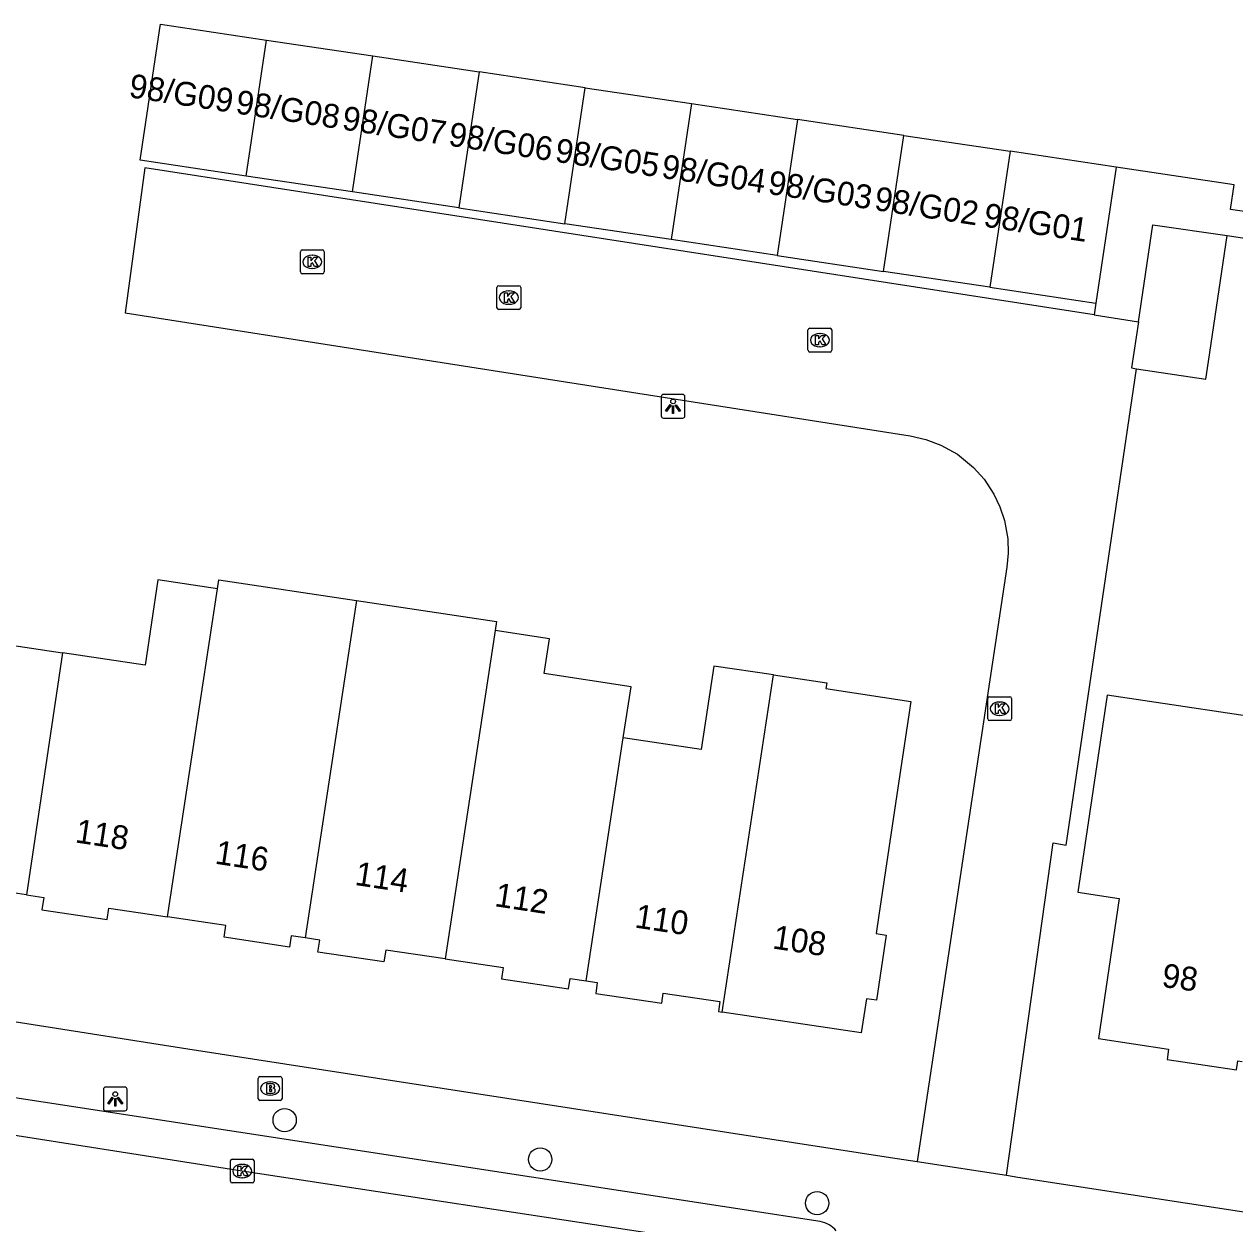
# Model space of a CAD drawing. Extents: x 161486 to 162249, y 379484 to 380829.
# Drawn here: x 161717.9 to 161768.8, y 380576 to 380626.4 of the extents above; entities that cross this region are included whole.
import ezdxf

# ---------------------------------------------------------------- set-up
doc = ezdxf.new("R2010")
doc.units = 0
for name, color, linetype in [('IMGEO_Boom', 7, 'Continuous'), ('IMGEO_Brandkraan', 7, 'Continuous'), ('IMGEO_Kolk', 7, 'Continuous'), ('IMGEO_Lichtpunt', 7, 'Continuous'), ('IMGEO_Pand', 7, 'Continuous'), ('IMGEO_Pand_nummerreeks', 7, 'Continuous'), ('IMGEO_Rijbaan_lokaal_open', 7, 'Continuous'), ('IMGEO_Voetpad_open', 7, 'Continuous')]:
    doc.layers.add(name, color=color, linetype=linetype)

msp = doc.modelspace()

# ---------------------------------------------------------------- linework, layer by layer
at = {"layer": 'IMGEO_Boom'}
for centre in [(161728.873, 380580.399), (161739.612, 380578.747), (161751.249, 380576.91)]:
    msp.add_circle(centre, 0.489, dxfattribs=at)
at = {"layer": 'IMGEO_Brandkraan'}
for p, q in [((161727.762, 380581.299), (161727.762, 380582.151)), ((161727.837, 380582.225), (161728.689, 380582.225)), ((161728.25, 380582.005), (161728.275, 380582.005)), ((161728.763, 380582.151), (161728.763, 380581.299)), ((161728.689, 380581.225), (161727.837, 380581.225)), ((161728.273, 380581.445), (161728.248, 380581.445))]:
    msp.add_line(p, q, dxfattribs=at)
for points in [[(161727.762, 380581.299), (161727.762, 380582.151)], [(161727.837, 380582.225), (161728.689, 380582.225)], [(161728.11, 380581.925), (161728.11, 380581.525), (161728.323, 380581.525)], [(161728.341, 380581.925), (161728.11, 380581.925)], [(161728.289, 380581.844), (161728.235, 380581.844), (161728.235, 380581.768)], [(161728.235, 380581.768), (161728.288, 380581.768)], [(161728.763, 380582.151), (161728.763, 380581.299)], [(161728.689, 380581.225), (161727.837, 380581.225)], [(161728.297, 380581.692), (161728.235, 380581.692), (161728.235, 380581.611)], [(161728.235, 380581.611), (161728.297, 380581.611)]]:
    msp.add_lwpolyline(points, dxfattribs=at)
for centre, radius, start, end in [((161727.839, 380582.149), 0.0765, 91.552, 178.448), ((161727.839, 380582.149), 0.0765, 91.552, 178.448), ((161728.29, 380581.806), 0.0379, 267.8285, 90.9355), ((161728.345, 380581.78), 0.145, 59.4692, 91.5367), ((161728.37, 380581.827), 0.0922, 285.5137, 58.1501), ((161728.375, 380581.635), 0.105, 301.3115, 78.989), ((161728.687, 380582.149), 0.0765, 1.552, 88.448), ((161728.687, 380582.149), 0.0765, 1.552, 88.448), ((161727.839, 380581.301), 0.0765, 181.552, 268.448), ((161727.839, 380581.301), 0.0765, 181.552, 268.448), ((161728.298, 380581.651), 0.0404, 269.8759, 90.5077), ((161728.329, 380581.776), 0.251, 268.6676, 293.5347), ((161728.687, 380581.301), 0.0765, 271.552, 358.448), ((161728.687, 380581.301), 0.0765, 271.552, 358.448)]:
    msp.add_arc(centre, radius, start, end, dxfattribs=at)
for centre, major_axis, ratio, start_param, end_param in [((161728.249, 380581.725), (-0.387, 0.002), 0.722429, 4.712389, 7.853982), ((161728.274, 380581.725), (-0.39, 0.002), 0.717154, 1.570796, 4.712389)]:
    msp.add_ellipse(centre, major_axis=major_axis, ratio=ratio, start_param=start_param, end_param=end_param, dxfattribs=at)
at = {"layer": 'IMGEO_Kolk'}
for p, q in [((161729.535, 380616.027), (161729.535, 380616.879)), ((161729.61, 380616.953), (161730.462, 380616.953)), ((161730.536, 380616.879), (161730.536, 380616.027)), ((161730.023, 380616.733), (161730.048, 380616.733)), ((161730.462, 380615.953), (161729.61, 380615.953)), ((161730.046, 380616.173), (161730.021, 380616.173)), ((161737.792, 380614.525), (161737.792, 380615.377)), ((161737.867, 380615.451), (161738.719, 380615.451)), ((161738.793, 380615.377), (161738.793, 380614.525)), ((161738.28, 380615.231), (161738.305, 380615.231)), ((161738.719, 380614.451), (161737.867, 380614.451)), ((161738.303, 380614.671), (161738.278, 380614.671)), ((161750.865, 380612.738), (161750.865, 380613.59)), ((161750.94, 380613.664), (161751.792, 380613.664)), ((161751.353, 380613.444), (161751.378, 380613.444)), ((161751.866, 380613.59), (161751.866, 380612.738)), ((161751.376, 380612.884), (161751.351, 380612.884)), ((161751.792, 380612.664), (161750.94, 380612.664)), ((161758.419, 380597.255), (161758.419, 380598.107)), ((161758.494, 380598.181), (161759.346, 380598.181)), ((161759.42, 380598.107), (161759.42, 380597.255)), ((161758.907, 380597.961), (161758.932, 380597.961)), ((161759.346, 380597.181), (161758.494, 380597.181)), ((161758.93, 380597.401), (161758.905, 380597.401)), ((161726.591, 380577.832), (161726.591, 380578.684)), ((161726.666, 380578.758), (161727.518, 380578.758)), ((161727.592, 380578.684), (161727.592, 380577.832)), ((161727.079, 380578.538), (161727.104, 380578.538)), ((161727.518, 380577.758), (161726.666, 380577.758)), ((161727.102, 380577.978), (161727.077, 380577.978))]:
    msp.add_line(p, q, dxfattribs=at)
for points in [[(161729.535, 380616.027), (161729.535, 380616.879)], [(161729.61, 380616.953), (161730.462, 380616.953)], [(161730.536, 380616.879), (161730.536, 380616.027)], [(161729.856, 380616.653), (161729.979, 380616.653), (161729.979, 380616.502), (161730.109, 380616.653), (161730.273, 380616.653), (161730.127, 380616.502), (161730.28, 380616.253), (161730.128, 380616.253), (161730.043, 380616.417), (161729.979, 380616.35), (161729.979, 380616.253), (161729.856, 380616.253), (161729.856, 380616.653)], [(161730.462, 380615.953), (161729.61, 380615.953)], [(161737.792, 380614.525), (161737.792, 380615.377)], [(161737.867, 380615.451), (161738.719, 380615.451)], [(161738.793, 380615.377), (161738.793, 380614.525)], [(161738.113, 380615.151), (161738.236, 380615.151), (161738.236, 380615), (161738.366, 380615.151), (161738.53, 380615.151), (161738.384, 380615), (161738.537, 380614.751), (161738.385, 380614.751), (161738.3, 380614.915), (161738.236, 380614.848), (161738.236, 380614.751), (161738.113, 380614.751), (161738.113, 380615.151)], [(161738.719, 380614.451), (161737.867, 380614.451)], [(161750.865, 380612.738), (161750.865, 380613.59)], [(161750.94, 380613.664), (161751.792, 380613.664)], [(161751.186, 380613.364), (161751.309, 380613.364), (161751.309, 380613.213), (161751.439, 380613.364), (161751.603, 380613.364), (161751.457, 380613.213), (161751.61, 380612.964), (161751.458, 380612.964), (161751.373, 380613.128), (161751.309, 380613.061), (161751.309, 380612.964), (161751.186, 380612.964), (161751.186, 380613.364)], [(161751.866, 380613.59), (161751.866, 380612.738)], [(161751.792, 380612.664), (161750.94, 380612.664)], [(161758.419, 380597.255), (161758.419, 380598.107)], [(161758.494, 380598.181), (161759.346, 380598.181)], [(161759.42, 380598.107), (161759.42, 380597.255)], [(161758.74, 380597.881), (161758.863, 380597.881), (161758.863, 380597.73), (161758.993, 380597.881), (161759.157, 380597.881), (161759.011, 380597.73), (161759.164, 380597.481), (161759.012, 380597.481), (161758.927, 380597.645), (161758.863, 380597.578), (161758.863, 380597.481), (161758.74, 380597.481), (161758.74, 380597.881)], [(161759.346, 380597.181), (161758.494, 380597.181)], [(161726.591, 380577.832), (161726.591, 380578.684)], [(161726.666, 380578.758), (161727.518, 380578.758)], [(161727.592, 380578.684), (161727.592, 380577.832)], [(161726.912, 380578.458), (161727.035, 380578.458), (161727.035, 380578.307), (161727.165, 380578.458), (161727.329, 380578.458), (161727.183, 380578.307), (161727.336, 380578.058), (161727.184, 380578.058), (161727.099, 380578.222), (161727.035, 380578.155), (161727.035, 380578.058), (161726.912, 380578.058), (161726.912, 380578.458)], [(161727.518, 380577.758), (161726.666, 380577.758)]]:
    msp.add_lwpolyline(points, dxfattribs=at)
for centre, start, end in [((161729.612, 380616.877), 91.552, 178.448), ((161729.612, 380616.877), 91.552, 178.448), ((161730.46, 380616.877), 1.552, 88.448), ((161730.46, 380616.877), 1.552, 88.448), ((161729.612, 380616.029), 181.552, 268.448), ((161729.612, 380616.029), 181.552, 268.448), ((161730.46, 380616.029), 271.552, 358.448), ((161730.46, 380616.029), 271.552, 358.448), ((161737.869, 380615.375), 91.552, 178.448), ((161737.869, 380615.375), 91.552, 178.448), ((161738.717, 380615.375), 1.552, 88.448), ((161738.717, 380615.375), 1.552, 88.448), ((161737.869, 380614.527), 181.552, 268.448), ((161737.869, 380614.527), 181.552, 268.448), ((161738.717, 380614.527), 271.552, 358.448), ((161738.717, 380614.527), 271.552, 358.448), ((161750.942, 380613.588), 91.552, 178.448), ((161750.942, 380613.588), 91.552, 178.448), ((161751.79, 380613.588), 1.552, 88.448), ((161751.79, 380613.588), 1.552, 88.448), ((161750.942, 380612.74), 181.552, 268.448), ((161750.942, 380612.74), 181.552, 268.448), ((161751.79, 380612.74), 271.552, 358.448), ((161751.79, 380612.74), 271.552, 358.448), ((161758.496, 380598.105), 91.552, 178.448), ((161758.496, 380598.105), 91.552, 178.448), ((161759.344, 380598.105), 1.552, 88.448), ((161759.344, 380598.105), 1.552, 88.448), ((161758.496, 380597.257), 181.552, 268.448), ((161758.496, 380597.257), 181.552, 268.448), ((161759.344, 380597.257), 271.552, 358.448), ((161759.344, 380597.257), 271.552, 358.448), ((161726.668, 380578.682), 91.552, 178.448), ((161726.668, 380578.682), 91.552, 178.448), ((161727.516, 380578.682), 1.552, 88.448), ((161727.516, 380578.682), 1.552, 88.448), ((161726.668, 380577.834), 181.552, 268.448), ((161726.668, 380577.834), 181.552, 268.448), ((161727.516, 380577.834), 271.552, 358.448), ((161727.516, 380577.834), 271.552, 358.448)]:
    msp.add_arc(centre, 0.0765, start, end, dxfattribs=at)
for centre, major_axis, ratio, start_param, end_param in [((161730.022, 380616.453), (-0.387, 0.002), 0.722429, 4.712389, 7.853982), ((161730.047, 380616.453), (-0.39, 0.002), 0.717154, 1.570796, 4.712389), ((161738.279, 380614.951), (-0.387, 0.002), 0.722429, 4.712389, 7.853982), ((161738.304, 380614.951), (-0.39, 0.002), 0.717154, 1.570796, 4.712389), ((161751.352, 380613.164), (-0.387, 0.002), 0.722429, 4.712389, 7.853982), ((161751.377, 380613.164), (-0.39, 0.002), 0.717154, 1.570796, 4.712389), ((161758.906, 380597.681), (-0.387, 0.002), 0.722429, 4.712389, 7.853982), ((161758.931, 380597.681), (-0.39, 0.002), 0.717154, 1.570796, 4.712389), ((161727.078, 380578.258), (-0.387, 0.002), 0.722429, 4.712389, 7.853982), ((161727.103, 380578.258), (-0.39, 0.002), 0.717154, 1.570796, 4.712389)]:
    msp.add_ellipse(centre, major_axis=major_axis, ratio=ratio, start_param=start_param, end_param=end_param, dxfattribs=at)
at = {"layer": 'IMGEO_Lichtpunt'}
for p, q in [((161744.697, 380610.79), (161744.697, 380609.983)), ((161744.697, 380610.79), (161744.697, 380609.983)), ((161745.599, 380610.885), (161744.791, 380610.885)), ((161745.599, 380610.885), (161744.791, 380610.885)), ((161745.693, 380609.983), (161745.693, 380610.79)), ((161745.693, 380609.983), (161745.693, 380610.79)), ((161744.791, 380609.889), (161745.599, 380609.889)), ((161744.791, 380609.889), (161745.599, 380609.889)), ((161722.158, 380581.789), (161721.35, 380581.789)), ((161722.158, 380581.789), (161721.35, 380581.789)), ((161721.256, 380581.694), (161721.256, 380580.887)), ((161721.256, 380581.694), (161721.256, 380580.887)), ((161722.252, 380580.887), (161722.252, 380581.694)), ((161722.252, 380580.887), (161722.252, 380581.694)), ((161721.35, 380580.793), (161722.158, 380580.793)), ((161721.35, 380580.793), (161722.158, 380580.793))]:
    msp.add_line(p, q, dxfattribs=at)
for points in [[(161745.071, 380610.454), (161745.11, 380610.426), (161744.922, 380610.164), (161744.884, 380610.191), (161745.071, 380610.454)], [(161745.173, 380610.406), (161745.22, 380610.406), (161745.22, 380610.084), (161745.173, 380610.084), (161745.173, 380610.406)], [(161745.283, 380610.426), (161745.321, 380610.453), (161745.508, 380610.191), (161745.469, 380610.163), (161745.283, 380610.426)], [(161721.63, 380581.358), (161721.669, 380581.33), (161721.481, 380581.068), (161721.443, 380581.095), (161721.63, 380581.358)], [(161721.732, 380581.31), (161721.779, 380581.31), (161721.779, 380580.988), (161721.732, 380580.988), (161721.732, 380581.31)], [(161721.842, 380581.33), (161721.88, 380581.357), (161722.067, 380581.095), (161722.028, 380581.067), (161721.842, 380581.33)]]:
    msp.add_lwpolyline(points, dxfattribs=at)
for centre in [(161745.196, 380610.588), (161721.755, 380581.492)]:
    msp.add_circle(centre, 0.0994, dxfattribs=at)
for centre, start, end in [((161744.791, 380610.79), 90, 180), ((161744.791, 380610.79), 90, 180), ((161745.599, 380610.79), 0, 90), ((161745.599, 380610.79), 0, 90), ((161744.791, 380609.983), 180, 270), ((161744.791, 380609.983), 180, 270), ((161745.599, 380609.983), 270, 0), ((161745.599, 380609.983), 270, 360), ((161721.35, 380581.694), 90, 180), ((161721.35, 380581.694), 90, 180), ((161722.158, 380581.694), 0, 90), ((161722.158, 380581.694), 0, 90), ((161721.35, 380580.887), 180, 270), ((161721.35, 380580.887), 180, 270), ((161722.158, 380580.887), 270, 0), ((161722.158, 380580.887), 270, 360)]:
    msp.add_arc(centre, 0.0946, start, end, dxfattribs=at)
at = {"layer": 'IMGEO_Pand'}
for points in [[(161727.261, 380620.058), (161722.798, 380620.725), (161723.613, 380626.176), (161723.652, 380626.435), (161728.115, 380625.768)], [(161727.261, 380620.058), (161728.115, 380625.768)], [(161728.115, 380625.768), (161732.578, 380625.101)], [(161731.724, 380619.39), (161732.578, 380625.101)], [(161732.578, 380625.101), (161737.041, 380624.434)], [(161737.041, 380624.434), (161736.187, 380618.723)], [(161741.504, 380623.767), (161737.041, 380624.434)], [(161740.65, 380618.056), (161741.504, 380623.767)], [(161741.504, 380623.767), (161745.967, 380623.099)], [(161745.967, 380623.099), (161745.113, 380617.389)], [(161745.967, 380623.099), (161750.43, 380622.432)], [(161750.43, 380622.432), (161749.576, 380616.722)], [(161754.893, 380621.765), (161750.43, 380622.432)], [(161754.039, 380616.054), (161754.893, 380621.765)], [(161754.893, 380621.765), (161759.356, 380621.098)], [(161759.356, 380621.098), (161758.502, 380615.387)], [(161763.819, 380620.431), (161759.356, 380621.098)], [(161763.819, 380620.431), (161762.965, 380614.72)], [(161731.724, 380619.39), (161727.261, 380620.058)], [(161736.187, 380618.723), (161731.724, 380619.39)], [(161736.187, 380618.723), (161740.65, 380618.056)], [(161745.113, 380617.389), (161740.65, 380618.056)], [(161764.751, 380613.935), (161765.359, 380618.012), (161768.486, 380617.565)], [(161749.576, 380616.722), (161745.113, 380617.389)], [(161764.673, 380611.963), (161767.585, 380611.529), (161767.696, 380612.271), (161768.486, 380617.565)], [(161749.576, 380616.722), (161754.039, 380616.054)], [(161758.502, 380615.387), (161754.039, 380616.054)], [(161758.502, 380615.387), (161762.965, 380614.72)], [(161764.751, 380613.935), (161764.462, 380611.994), (161764.673, 380611.963)], [(161718.025, 380589.859), (161717.444, 380589.946), (161717.374, 380589.474), (161714.61, 380589.887), (161714.678, 380590.34), (161712.018, 380590.738), (161712.757, 380595.684), (161714.076, 380604.503), (161716.615, 380604.124), (161716.079, 380600.544), (161719.544, 380600.026)], [(161726.052, 380602.721), (161723.546, 380603.095), (161723.01, 380599.508), (161719.544, 380600.026)], [(161726.052, 380602.721), (161726.109, 380603.096), (161731.896, 380602.231)], [(161723.951, 380588.939), (161726.052, 380602.721)], [(161731.896, 380602.231), (161731.292, 380598.274), (161729.733, 380588.055)], [(161731.896, 380602.231), (161737.778, 380601.351), (161737.719, 380600.964)], [(161737.719, 380600.964), (161735.616, 380587.17)], [(161743.1, 380596.454), (161743.428, 380598.604), (161739.782, 380599.16), (161740.001, 380600.622), (161737.719, 380600.964)], [(161719.544, 380600.026), (161718.025, 380589.859)], [(161749.417, 380599.1), (161746.908, 380599.475), (161746.383, 380595.963), (161743.1, 380596.454)], [(161747.257, 380584.939), (161749.417, 380599.1)], [(161749.417, 380599.1), (161751.654, 380598.765), (161751.618, 380598.528), (161755.186, 380597.979), (161754.686, 380594.639), (161753.844, 380589.01), (161753.729, 380588.238), (161754.154, 380588.174), (161753.745, 380585.435), (161753.319, 380585.498), (161753.105, 380584.064), (161747.257, 380584.939)], [(161771.49, 380597.045), (161763.435, 380598.249), (161762.198, 380589.969), (161763.948, 380589.708), (161763.069, 380583.823), (161766.019, 380583.382), (161765.954, 380582.941), (161768.871, 380582.505), (161768.928, 380582.885), (161769.114, 380582.857)], [(161741.544, 380586.25), (161743.1, 380596.454)], [(161718.025, 380589.859), (161718.751, 380589.75), (161718.674, 380589.233), (161721.415, 380588.823), (161721.487, 380589.307), (161723.951, 380588.939)], [(161729.733, 380588.055), (161729.143, 380588.143), (161729.072, 380587.669), (161726.325, 380588.079), (161726.399, 380588.573), (161723.951, 380588.939)], [(161735.616, 380587.17), (161733.122, 380587.543), (161733.047, 380587.045), (161730.269, 380587.46), (161730.345, 380587.963), (161729.733, 380588.055)], [(161735.616, 380587.17), (161738.054, 380586.806), (161737.983, 380586.33), (161740.8, 380585.909), (161740.866, 380586.351), (161741.544, 380586.25)], [(161741.544, 380586.25), (161742.012, 380586.18), (161741.944, 380585.724), (161744.721, 380585.309), (161744.785, 380585.738), (161747.164, 380585.382), (161747.101, 380584.962), (161747.257, 380584.939)]]:
    msp.add_lwpolyline(points, dxfattribs=at)
at = {"layer": 'IMGEO_Rijbaan_lokaal_open'}
for points in [[(161762.888, 380614.224), (161722.998, 380620.409), (161722.17, 380614.317), (161755.152, 380609.143), (161755.815, 380608.996), (161756.451, 380608.757), (161757.141, 380608.37), (161757.82, 380607.818), (161758.262, 380607.322), (161758.674, 380606.698), (161758.929, 380606.161), (161759.121, 380605.582), (161759.258, 380604.817), (161759.278, 380604.221), (161759.226, 380603.627), (161755.449, 380578.66)], [(161762.888, 380614.224), (161764.751, 380613.935)], [(161759.209, 380578.08), (161761.171, 380592.041), (161761.717, 380591.955), (161764.673, 380611.963)], [(161748.16, 380575.062), (161745.481, 380575.457), (161727.091, 380578.257), (161706.209, 380581.535), (161684.371, 380584.84), (161680.794, 380585.397)], [(161755.449, 380578.66), (161759.209, 380578.08)]]:
    msp.add_lwpolyline(points, dxfattribs=at)
at = {"layer": 'IMGEO_Voetpad_open'}
for points in [[(161798.865, 380614.315), (161768.624, 380618.651), (161768.779, 380619.69), (161763.819, 380620.431)], [(161768.486, 380617.565), (161772.686, 380616.922), (161777.083, 380616.222), (161784.042, 380615.157), (161784.905, 380615.016)], [(161762.965, 380614.72), (161762.888, 380614.224)], [(161751.383, 380576.136), (161706.575, 380583.016), (161683.607, 380586.497)], [(161711.262, 380585.528), (161724.808, 380583.386), (161754.33, 380578.833), (161755.449, 380578.66)], [(161759.209, 380578.08), (161759.686, 380578.007), (161785.522, 380574.037), (161840.43, 380565.564)]]:
    msp.add_lwpolyline(points, dxfattribs=at)
msp.add_arc((161751.185, 380575.015), 1.138, 40.2052, 79.9746, dxfattribs=at)

# ---------------------------------------------------------------- texts
at = {"layer": 'IMGEO_Pand_nummerreeks'}
for s, rotation, p in [('98/G09', 351.3997, (161722.295, 380623.373)), ('98/G08', 351.3997, (161726.776, 380622.695)), ('98/G07', 351.3997, (161731.247, 380622.019)), ('98/G06', 351.3997, (161735.722, 380621.342)), ('98/G05', 351.3997, (161740.197, 380620.665)), ('98/G04', 351.3997, (161744.672, 380619.988)), ('98/G03', 351.3997, (161749.146, 380619.312)), ('98/G02', 351.3997, (161753.615, 380618.636)), ('98/G01', 351.3997, (161758.205, 380617.942)), ('118', 351.3577, (161720.035, 380592.069)), ('116', 351.3598, (161725.911, 380591.175)), ('114', 351.3598, (161731.79, 380590.282)), ('112', 351.3598, (161737.664, 380589.389)), ('110', 351.3577, (161743.549, 380588.495)), ('108', 351.3577, (161749.338, 380587.614)), ('98', 352.0732, (161765.699, 380586.001))]:
    msp.add_text(s, height=1, rotation=rotation, dxfattribs=at).set_placement(p)

doc.saveas('drawing.dxf')
